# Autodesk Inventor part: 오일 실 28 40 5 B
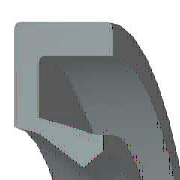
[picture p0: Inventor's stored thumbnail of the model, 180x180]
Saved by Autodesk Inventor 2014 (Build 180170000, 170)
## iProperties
IsCustomPart: 1
Created: 2012-02
Part Number: 오일 실 28 40 5 B
Material: 고무
Description: 오일 실 - 비스프링, 조립 GA
Document SubType Name: Modeling
Standard: JIS B 2402
Designer: mduedu
Standards Organization: JIS
Language: ko-KR
Size Designation: 28 40 5 B
Categories: <MemberInstance><Categories><Category DisplayName="샤프트 부품" InternalName="7f7aeb1f-a693-4053-b835-cee3144e0d98" Mnemonic="SHFT"><Category DisplayName="실링" Intern
Density: 0.93 g/cm^3
Appearance: Rubber-Black
Author: mduedu
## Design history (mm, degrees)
body "Solid1"
revolve "회전1" stored, may be unused: angle "d27" = 360 deg
fillet "모깎기1" dims "d28" = 0.25 (= 0.05 x b)
sketch "스케치2"
  geometry: L1 (15.971, -3.75)-(16.571, -5); L2 (15.171, -3.438)-(15.971, -3.75); L3 (14, -1.375)-(15.171, -3.438); L4 (14.923, -0.75)-(14, -1.375); L5 (17.6, -4.375)-(14.923, -0.75); L6 (17.6, -0.25)-(17.6, -4.375); L7 (18.8, -0.25)-(17.6, -0.25); L8 (18.8, 0)-(18.8, -0.25); L9 (20, 0)-(18.8, 0); L10 (20, -5)-(20, 0); L11 (16.571, -5)-(20, -5); L12 (0, -9.6)-(0, 1.6) reference; L13 (28, 0)-(14, 0) reference
  constraints: 22 end point, 3 horizontal, 3 vertical
  dimensions: "d2" = 5 distance of L10.start L9.start (= b); "d4" = 1.2 distance of L9.start L8.start (= 0.1 x dd - 0.1 x Diam); "d6" = 0.25 distance of L8.start L7.start (= 0.05 x b); "d8" = 0.92308 horizontal distance of L4.start L3.start (= 0.0769231 x dd - 0.0769231 x Diam); "d10" = 0.625 vertical distance of L5.start L10.start (= 0.125 x b); "d12" = 1.2 distance of L7.start L6.start (= 0.1 x dd - 0.1 x Diam); "d14" = 0.5 vertical distance of L4.start L6.start (= 0.1 x b); "d16" = 3.42857 distance of L1.end L10.start (= 0.285714 x dd - 0.285714 x Diam); "d18" = 0.6 horizontal distance of L1.start L1.end (= 0.05 x dd - 0.05 x Diam); "d20" = 0.625 vertical distance of L4.start L3.start (= 0.125 x b); "d22" = 1.25 vertical distance of L1.start L1.end (= 0.25 x b); "d24" = 0.8 horizontal distance of L2.start L1.start (= 0.0666667 x dd - 0.0666667 x Diam); "d26" = 0.3125 vertical distance of L2.start L1.start (= 0.0625 x b); "d29" = 0 distance between parallel lines of L13 L9; "d30" = 14 distance from line of L3.start L12 (= 0.5 x Diam); "d31" = 20 distance between parallel lines of L12 L10 (= 0.5 x dd)
other parameters: "Diam" = 28 [user parameter; used in 7 equation terms], "b" = 5 [user parameter; used in 8 equation terms], "d1" = 8 (derived), "d3" = 2 (derived), "d5" = 0.4 (derived), "d7" = 1.53846 (derived), "d9" = 1 (derived), "d11" = 2 (derived), "d13" = 0.8 (derived), "d15" = 5.71429 (derived), "d17" = 1 (derived), "d19" = 1 (derived), "d21" = 2 (derived), "d23" = 1.33333 (derived), "d25" = 0.5 (derived), "d32" = 0
